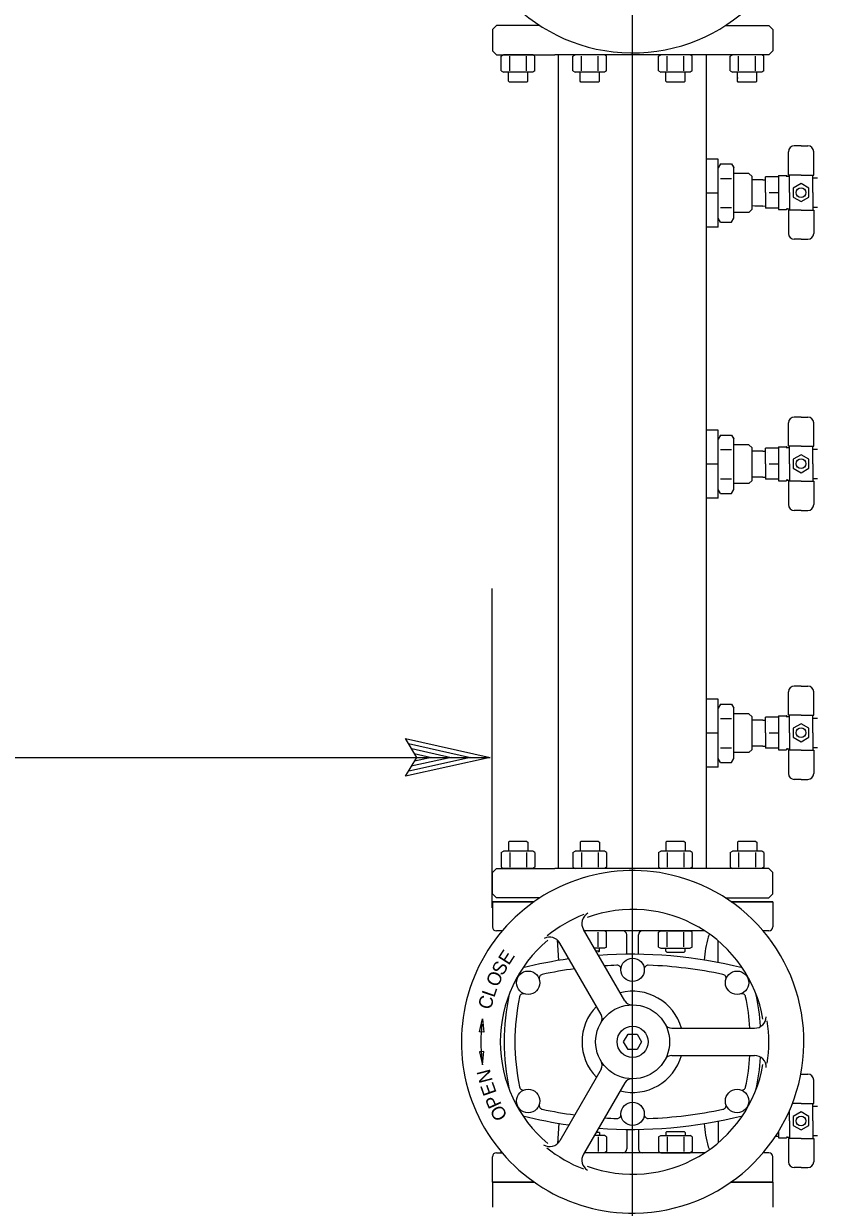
# Model space of a CAD drawing. Extents: x -1680 to 1155, y -802 to 799.
# Drawn here: x 260.1 to 316.4, y -477.7 to -393.8 of the extents above; entities that cross this region are included whole.
import ezdxf

# ---------------------------------------------------------------- set-up
doc = ezdxf.new("R2010")
doc.units = 0
doc.layers.add('Misc CnstDet(22)', color=7, linetype='Continuous')

msp = doc.modelspace()

# ---------------------------------------------------------------- linework, layer by layer
at = {"layer": 'Misc CnstDet(22)'}
for p, q in [((303.253, -548.827), (303.253, -300.878)), ((293.328, -394.194), (293.604, -393.918)), ((293.328, -394.194), (293.328, -395.711)), ((296.691, -393.918), (293.604, -393.918)), ((309.83, -393.918), (312.917, -393.918)), ((312.917, -393.918), (313.193, -394.194)), ((313.193, -394.194), (313.193, -395.711)), ((293.328, -395.711), (293.604, -395.987)), ((313.193, -395.711), (312.917, -395.987)), ((293.604, -395.987), (297.742, -395.987)), ((293.951, -396.08), (294.111, -395.987)), ((293.951, -397.131), (293.951, -396.08)), ((296.18, -395.987), (294.111, -395.987)), ((294.548, -397.128), (294.548, -396.082)), ((295.743, -397.128), (295.743, -396.082)), ((296.34, -396.08), (296.18, -395.987)), ((296.34, -397.131), (296.34, -396.08)), ((303.26, -395.987), (297.742, -395.987)), ((298.018, -397.253), (298.018, -395.987)), ((299.028, -396.08), (299.188, -395.987)), ((299.028, -397.131), (299.028, -396.08)), ((301.257, -395.987), (299.188, -395.987)), ((299.625, -397.128), (299.625, -396.082)), ((300.82, -397.128), (300.82, -396.082)), ((301.417, -396.08), (301.257, -395.987)), ((301.417, -397.131), (301.417, -396.08)), ((312.917, -395.987), (303.26, -395.987)), ((305.104, -396.08), (305.264, -395.987)), ((305.104, -397.131), (305.104, -396.08)), ((307.333, -395.987), (305.264, -395.987)), ((305.701, -397.128), (305.701, -396.082)), ((306.896, -397.128), (306.896, -396.082)), ((307.493, -396.08), (307.333, -395.987)), ((307.493, -397.131), (307.493, -396.08)), ((308.503, -397.253), (308.503, -395.987)), ((310.181, -396.08), (310.341, -395.987)), ((310.181, -397.131), (310.181, -396.08)), ((312.41, -395.987), (310.341, -395.987)), ((310.778, -397.128), (310.778, -396.082)), ((311.973, -397.128), (311.973, -396.082)), ((312.57, -396.08), (312.41, -395.987)), ((312.57, -397.131), (312.57, -396.08)), ((293.951, -397.131), (294.111, -397.223)), ((296.18, -397.223), (294.111, -397.223)), ((294.456, -397.852), (294.456, -397.223)), ((295.835, -397.852), (295.835, -397.223)), ((296.34, -397.131), (296.18, -397.223)), ((298.018, -453.652), (298.018, -397.253)), ((299.028, -397.131), (299.188, -397.223)), ((301.257, -397.223), (299.188, -397.223)), ((299.533, -397.852), (299.533, -397.223)), ((300.912, -397.852), (300.912, -397.223)), ((301.417, -397.131), (301.257, -397.223)), ((305.104, -397.131), (305.264, -397.223)), ((307.333, -397.223), (305.264, -397.223)), ((305.609, -397.852), (305.609, -397.223)), ((306.988, -397.852), (306.988, -397.223)), ((307.493, -397.131), (307.333, -397.223)), ((308.503, -453.652), (308.503, -397.253)), ((310.181, -397.131), (310.341, -397.223)), ((312.41, -397.223), (310.341, -397.223)), ((310.686, -397.852), (310.686, -397.223)), ((312.065, -397.852), (312.065, -397.223)), ((312.57, -397.131), (312.41, -397.223)), ((294.522, -397.918), (294.456, -397.852)), ((295.769, -397.918), (294.522, -397.918)), ((295.769, -397.918), (295.835, -397.852)), ((299.599, -397.918), (299.533, -397.852)), ((300.846, -397.918), (299.599, -397.918)), ((300.846, -397.918), (300.912, -397.852)), ((305.675, -397.918), (305.609, -397.852)), ((306.922, -397.918), (305.675, -397.918)), ((306.922, -397.918), (306.988, -397.852)), ((310.752, -397.664), (310.686, -397.597)), ((310.752, -397.918), (310.686, -397.852)), ((311.999, -397.918), (310.752, -397.918)), ((311.999, -397.918), (312.065, -397.852)), ((315.202, -402.437), (314.722, -402.437)), ((315.202, -402.437), (315.682, -402.437)), ((309.33, -403.37), (308.503, -403.37)), ((309.33, -408.198), (309.33, -403.37)), ((314.308, -404.506), (314.308, -402.851)), ((316.096, -404.506), (316.096, -402.851)), ((309.491, -403.722), (309.33, -404)), ((309.491, -403.722), (310.274, -403.722)), ((310.274, -403.722), (310.434, -404)), ((310.36, -403.853), (310.434, -403.982)), ((310.434, -407.568), (310.434, -403.982)), ((310.434, -407.568), (310.434, -403.982)), ((309.495, -404.74), (310.27, -404.74)), ((311.506, -404.396), (310.434, -404.397)), ((311.725, -404.616), (311.506, -404.396)), ((311.725, -406.934), (311.725, -404.616)), ((311.932, -404.848), (311.725, -404.854)), ((312.484, -404.848), (311.932, -404.848)), ((312.484, -404.848), (312.691, -404.854)), ((312.691, -405.748), (312.691, -404.644)), ((313.596, -404.644), (312.691, -404.644)), ((312.802, -404.954), (312.802, -404.954)), ((313.596, -404.644), (313.455, -404.644)), ((313.596, -404.544), (313.596, -406.952)), ((313.596, -404.544), (314.15, -404.544)), ((314.198, -404.544), (314.198, -404.544)), ((314.198, -404.644), (314.198, -404.578)), ((314.236, -404.596), (314.374, -404.596)), ((315.202, -404.506), (314.308, -404.506)), ((314.374, -405.748), (314.374, -404.506)), ((315.202, -404.506), (316.096, -404.506)), ((316.03, -405.748), (316.03, -404.506)), ((316.039, -404.713), (316.356, -404.713)), ((309.33, -405.784), (308.503, -405.784)), ((312.691, -405.748), (312.691, -406.852)), ((312.943, -405.748), (313.596, -405.748)), ((314.374, -405.748), (314.374, -406.99)), ((316.03, -405.748), (316.03, -406.99)), ((311.932, -406.702), (311.725, -406.696)), ((312.484, -406.702), (311.932, -406.702)), ((312.484, -406.702), (312.691, -406.696)), ((316.039, -406.783), (316.356, -406.783)), ((309.491, -407.846), (309.33, -407.568)), ((309.495, -406.81), (310.27, -406.81)), ((310.274, -407.846), (310.434, -407.568)), ((311.506, -407.153), (310.434, -407.153)), ((311.725, -406.934), (311.506, -407.153)), ((313.596, -406.852), (312.691, -406.852)), ((312.802, -406.808), (312.802, -406.808)), ((313.596, -406.952), (314.15, -406.952)), ((314.198, -406.852), (314.198, -406.918)), ((314.236, -406.9), (314.374, -406.9)), ((314.308, -406.99), (314.308, -408.645)), ((315.202, -406.99), (314.308, -406.99)), ((315.202, -406.99), (316.096, -406.99)), ((316.096, -406.99), (316.096, -408.645)), ((309.33, -408.198), (308.503, -408.198)), ((309.491, -407.846), (310.274, -407.846)), ((315.202, -409.059), (314.722, -409.059)), ((315.202, -409.059), (315.682, -409.059)), ((315.202, -421.653), (314.722, -421.653)), ((315.202, -421.653), (315.682, -421.653)), ((309.33, -422.586), (308.503, -422.586)), ((309.33, -427.414), (309.33, -422.586)), ((314.308, -423.722), (314.308, -422.067)), ((316.096, -423.722), (316.096, -422.067)), ((309.491, -422.938), (309.33, -423.216)), ((309.491, -422.938), (310.274, -422.938)), ((310.274, -422.938), (310.434, -423.216)), ((310.36, -423.069), (310.434, -423.198)), ((310.434, -426.784), (310.434, -423.198)), ((310.434, -426.784), (310.434, -423.198)), ((309.495, -423.956), (310.27, -423.956)), ((311.506, -423.613), (310.434, -423.613)), ((311.725, -423.832), (311.506, -423.613)), ((311.725, -426.15), (311.725, -423.832)), ((311.932, -424.064), (311.725, -424.07)), ((312.484, -424.064), (311.932, -424.064)), ((312.484, -424.064), (312.691, -424.07)), ((312.691, -424.964), (312.691, -423.86)), ((313.596, -423.86), (312.691, -423.86)), ((312.802, -424.17), (312.802, -424.17)), ((313.596, -423.86), (313.455, -423.86)), ((313.596, -423.76), (313.596, -426.168)), ((313.596, -423.76), (314.15, -423.76)), ((314.198, -423.76), (314.198, -423.76)), ((314.198, -423.86), (314.198, -423.794)), ((314.236, -423.812), (314.374, -423.812)), ((315.202, -423.722), (314.308, -423.722)), ((314.374, -424.964), (314.374, -423.722)), ((315.202, -423.722), (316.096, -423.722)), ((316.03, -424.964), (316.03, -423.722)), ((316.039, -423.929), (316.356, -423.929)), ((309.33, -425), (308.503, -425)), ((312.691, -424.964), (312.691, -426.068)), ((312.943, -424.964), (313.596, -424.964)), ((314.374, -424.964), (314.374, -426.206)), ((316.03, -424.964), (316.03, -426.206)), ((309.495, -426.026), (310.27, -426.026)), ((311.932, -425.918), (311.725, -425.912)), ((312.484, -425.918), (311.932, -425.918)), ((312.484, -425.918), (312.691, -425.912)), ((313.596, -426.068), (312.691, -426.068)), ((312.802, -426.024), (312.802, -426.024)), ((314.198, -426.068), (314.198, -426.134)), ((316.039, -425.999), (316.356, -425.999)), ((309.491, -427.062), (309.33, -426.784)), ((310.274, -427.062), (310.434, -426.784)), ((311.506, -426.37), (310.434, -426.369)), ((311.725, -426.15), (311.506, -426.37)), ((313.596, -426.168), (314.15, -426.168)), ((314.236, -426.116), (314.374, -426.116)), ((314.308, -426.206), (314.308, -427.861)), ((315.202, -426.206), (314.308, -426.206)), ((315.202, -426.206), (316.096, -426.206)), ((316.096, -426.206), (316.096, -427.861)), ((309.33, -427.414), (308.503, -427.414)), ((309.491, -427.062), (310.274, -427.062)), ((315.202, -428.275), (314.722, -428.275)), ((315.202, -428.275), (315.682, -428.275)), ((293.292, -433.812), (293.292, -456.425)), ((314.308, -442.784), (314.308, -441.128)), ((315.202, -440.714), (314.722, -440.714)), ((315.202, -440.714), (315.682, -440.714)), ((316.096, -442.784), (316.096, -441.128)), ((309.33, -441.647), (308.503, -441.647)), ((309.33, -446.475), (309.33, -441.647)), ((309.491, -442), (309.33, -442.277)), ((309.491, -442), (310.274, -442)), ((310.274, -442), (310.434, -442.277)), ((310.36, -442.13), (310.434, -442.259)), ((310.434, -445.845), (310.434, -442.259)), ((310.434, -445.845), (310.434, -442.259)), ((311.506, -442.674), (310.434, -442.674)), ((311.725, -442.893), (311.506, -442.674)), ((313.596, -442.821), (313.596, -445.229)), ((313.596, -442.821), (314.15, -442.821)), ((314.198, -442.821), (314.198, -442.821)), ((314.198, -442.921), (314.198, -442.855)), ((315.202, -442.784), (314.308, -442.784)), ((314.374, -444.025), (314.374, -442.784)), ((315.202, -442.784), (316.096, -442.784)), ((316.03, -444.025), (316.03, -442.784)), ((309.495, -443.017), (310.27, -443.017)), ((311.725, -445.211), (311.725, -442.893)), ((311.932, -443.125), (311.725, -443.131)), ((312.484, -443.125), (311.932, -443.125)), ((312.484, -443.125), (312.691, -443.131)), ((312.691, -444.025), (312.691, -442.921)), ((313.596, -442.921), (312.691, -442.921)), ((312.802, -443.231), (312.802, -443.231)), ((313.596, -442.921), (313.455, -442.921)), ((314.236, -442.873), (314.374, -442.873)), ((316.039, -442.99), (316.356, -442.99)), ((287.955, -445.777), (287.155, -444.437)), ((287.155, -444.437), (287.155, -444.437)), ((287.155, -444.437), (293.155, -445.777)), ((309.33, -444.061), (308.503, -444.061)), ((312.691, -444.025), (312.691, -445.129)), ((312.943, -444.025), (313.596, -444.025)), ((314.374, -444.025), (314.374, -445.267)), ((316.03, -444.025), (316.03, -445.267)), ((287.372, -444.793), (291.775, -445.776)), ((287.606, -445.152), (290.393, -445.775)), ((309.495, -445.088), (310.27, -445.088)), ((311.725, -445.211), (311.506, -445.431)), ((311.932, -444.979), (311.725, -444.973)), ((312.484, -444.979), (311.932, -444.979)), ((312.484, -444.979), (312.691, -444.973)), ((313.596, -445.129), (312.691, -445.129)), ((312.802, -445.085), (312.802, -445.085)), ((313.596, -445.229), (314.15, -445.229)), ((314.198, -445.129), (314.198, -445.195)), ((314.236, -445.177), (314.374, -445.177)), ((314.308, -445.267), (314.308, -446.922)), ((315.202, -445.267), (314.308, -445.267)), ((315.202, -445.267), (316.096, -445.267)), ((316.039, -445.06), (316.356, -445.06)), ((316.096, -445.267), (316.096, -446.922)), ((212.088, -445.777), (293.155, -445.777)), ((293.155, -445.777), (287.155, -447.107)), ((287.155, -447.107), (287.955, -445.777)), ((291.764, -445.78), (287.39, -446.748)), ((290.393, -445.775), (287.567, -446.401)), ((287.782, -445.499), (289.011, -445.774)), ((289.011, -445.774), (287.802, -446.041)), ((293.155, -445.777), (293.155, -445.777)), ((309.491, -446.123), (309.33, -445.845)), ((309.491, -446.123), (310.274, -446.123)), ((310.274, -446.123), (310.434, -445.845)), ((311.506, -445.431), (310.434, -445.43)), ((309.33, -446.475), (308.503, -446.475)), ((287.155, -447.107), (287.155, -447.107)), ((315.202, -447.336), (314.722, -447.336)), ((315.202, -447.336), (315.682, -447.336)), ((294.522, -451.721), (294.456, -451.787)), ((294.456, -451.787), (294.456, -452.416)), ((295.769, -451.721), (294.522, -451.721)), ((295.769, -451.721), (295.835, -451.787)), ((295.835, -451.787), (295.835, -452.416)), ((299.599, -451.721), (299.533, -451.787)), ((299.533, -451.787), (299.533, -452.416)), ((300.846, -451.721), (299.599, -451.721)), ((300.846, -451.721), (300.912, -451.787)), ((300.912, -451.787), (300.912, -452.416)), ((305.675, -451.721), (305.609, -451.787)), ((305.609, -451.787), (305.609, -452.416)), ((306.922, -451.721), (305.675, -451.721)), ((306.922, -451.721), (306.988, -451.787)), ((306.988, -451.787), (306.988, -452.416)), ((310.752, -451.721), (310.686, -451.787)), ((310.686, -451.787), (310.686, -452.416)), ((311.999, -451.721), (310.752, -451.721)), ((311.999, -451.721), (312.065, -451.787)), ((312.065, -451.787), (312.065, -452.416)), ((293.951, -452.508), (294.111, -452.416)), ((293.951, -452.508), (293.951, -453.559)), ((296.18, -452.416), (294.111, -452.416)), ((294.548, -452.51), (294.548, -453.557)), ((295.743, -452.51), (295.743, -453.557)), ((296.34, -452.508), (296.18, -452.416)), ((296.34, -452.508), (296.34, -453.559)), ((299.028, -452.508), (299.188, -452.416)), ((299.028, -452.508), (299.028, -453.559)), ((301.257, -452.416), (299.188, -452.416)), ((299.625, -452.51), (299.625, -453.557)), ((300.82, -452.51), (300.82, -453.557)), ((301.417, -452.508), (301.257, -452.416)), ((301.417, -452.508), (301.417, -453.559)), ((305.104, -452.508), (305.264, -452.416)), ((305.104, -452.508), (305.104, -453.559)), ((307.333, -452.416), (305.264, -452.416)), ((305.701, -452.51), (305.701, -453.557)), ((306.896, -452.51), (306.896, -453.557)), ((307.493, -452.508), (307.333, -452.416)), ((307.493, -452.508), (307.493, -453.559)), ((310.181, -452.508), (310.341, -452.416)), ((310.181, -452.508), (310.181, -453.559)), ((312.41, -452.416), (310.341, -452.416)), ((310.778, -452.51), (310.778, -453.557)), ((311.973, -452.51), (311.973, -453.557)), ((312.57, -452.508), (312.41, -452.416)), ((312.57, -452.508), (312.57, -453.559)), ((293.328, -453.927), (293.604, -453.652)), ((293.604, -453.652), (297.742, -453.652)), ((293.951, -453.559), (294.111, -453.652)), ((296.18, -453.652), (294.111, -453.652)), ((296.34, -453.559), (296.18, -453.652)), ((312.917, -453.652), (297.742, -453.652)), ((299.028, -453.559), (299.188, -453.652)), ((301.257, -453.652), (299.188, -453.652)), ((301.417, -453.559), (301.257, -453.652)), ((305.104, -453.559), (305.264, -453.652)), ((307.333, -453.652), (305.264, -453.652)), ((307.493, -453.559), (307.333, -453.652)), ((310.181, -453.559), (310.341, -453.652)), ((312.41, -453.652), (310.341, -453.652)), ((312.57, -453.559), (312.41, -453.652)), ((313.193, -453.927), (312.917, -453.652)), ((293.328, -455.445), (293.328, -453.927)), ((313.193, -455.445), (313.193, -453.927)), ((293.328, -455.445), (293.604, -455.721)), ((296.281, -455.997), (293.328, -455.997)), ((293.328, -455.997), (293.328, -457.79)), ((293.328, -455.997), (296.281, -455.997)), ((293.328, -455.997), (296.281, -455.997)), ((296.691, -455.721), (293.604, -455.721)), ((309.83, -455.721), (312.917, -455.721)), ((313.193, -455.997), (310.24, -455.997)), ((310.24, -455.997), (313.193, -455.997)), ((310.24, -455.997), (313.193, -455.997)), ((312.917, -455.721), (313.193, -455.445)), ((313.193, -455.997), (313.193, -457.79)), ((302.704, -463.033), (299.774, -457.96)), ((294.011, -458.066), (293.604, -458.066)), ((298.027, -460.158), (297.926, -458.712)), ((308.376, -458.066), (299.836, -458.066)), ((301.257, -458.066), (299.836, -458.066)), ((300.82, -459.207), (300.82, -458.161)), ((301.417, -458.159), (301.257, -458.066)), ((301.417, -459.21), (301.417, -458.159)), ((302.847, -459.724), (302.847, -458.342)), ((303.674, -459.724), (303.674, -458.342)), ((305.104, -458.159), (305.264, -458.066)), ((305.104, -459.21), (305.104, -458.159)), ((305.264, -458.066), (307.333, -458.066)), ((305.701, -459.207), (305.701, -458.161)), ((306.896, -459.207), (306.896, -458.161)), ((307.493, -458.159), (307.333, -458.066)), ((307.493, -459.21), (307.493, -458.159)), ((309.33, -460.31), (309.33, -458.777)), ((312.917, -458.066), (312.51, -458.066)), ((301.031, -463.999), (298.102, -458.925)), ((301.257, -459.302), (300.549, -459.302)), ((300.912, -459.512), (300.67, -459.512)), ((300.846, -459.578), (300.912, -459.512)), ((300.912, -459.512), (300.912, -459.302)), ((301.417, -459.21), (301.257, -459.302)), ((305.104, -459.21), (305.264, -459.302)), ((305.264, -459.302), (307.333, -459.302)), ((305.609, -459.512), (305.609, -459.302)), ((305.675, -459.578), (305.609, -459.512)), ((305.675, -459.578), (306.922, -459.578)), ((306.922, -459.578), (306.988, -459.512)), ((306.988, -459.512), (306.988, -459.302)), ((307.493, -459.21), (307.333, -459.302)), ((306.047, -464.964), (311.905, -464.964)), ((306.047, -466.895), (311.905, -466.895)), ((301.031, -467.86), (298.102, -472.933)), ((302.704, -468.825), (299.774, -473.899)), ((315.202, -468.221), (315.182, -468.221)), ((315.202, -468.221), (315.682, -468.221)), ((316.096, -470.29), (316.096, -468.635)), ((315.202, -470.29), (314.59, -470.29)), ((315.202, -470.29), (316.096, -470.29)), ((316.03, -471.532), (316.03, -470.29)), ((316.039, -470.497), (316.356, -470.497)), ((314.374, -471.532), (314.374, -470.814)), ((298.027, -471.701), (297.926, -473.147)), ((302.847, -472.135), (302.847, -473.517)), ((303.674, -472.135), (303.674, -473.517)), ((309.33, -471.549), (309.33, -473.082)), ((314.374, -471.532), (314.374, -472.774)), ((316.03, -471.532), (316.03, -472.774)), ((301.257, -472.557), (300.549, -472.557)), ((300.912, -472.347), (300.67, -472.347)), ((300.82, -472.652), (300.82, -473.698)), ((300.912, -472.347), (300.912, -472.557)), ((301.417, -472.649), (301.257, -472.557)), ((301.417, -472.649), (301.417, -473.7)), ((305.104, -472.649), (305.264, -472.557)), ((305.104, -472.649), (305.104, -473.7)), ((305.264, -472.557), (307.333, -472.557)), ((305.675, -472.281), (305.609, -472.347)), ((305.609, -472.347), (305.609, -472.557)), ((305.675, -472.281), (306.922, -472.281)), ((305.701, -472.652), (305.701, -473.698)), ((306.896, -472.652), (306.896, -473.698)), ((306.922, -472.281), (306.988, -472.347)), ((306.988, -472.347), (306.988, -472.557)), ((307.493, -472.649), (307.333, -472.557)), ((307.493, -472.649), (307.493, -473.7)), ((313.596, -472.636), (313.38, -472.636)), ((313.596, -472.297), (313.596, -472.736)), ((313.596, -472.736), (314.15, -472.736)), ((314.198, -472.636), (314.198, -472.702)), ((314.236, -472.684), (314.374, -472.684)), ((314.308, -472.774), (314.308, -474.429)), ((315.202, -472.774), (314.308, -472.774)), ((315.202, -472.774), (316.096, -472.774)), ((316.039, -472.567), (316.356, -472.567)), ((316.096, -472.774), (316.096, -474.429)), ((293.604, -473.793), (294.011, -473.793)), ((293.951, -473.793), (293.951, -473.721)), ((308.376, -473.793), (299.836, -473.793)), ((301.257, -473.793), (299.836, -473.793)), ((301.417, -473.7), (301.257, -473.793)), ((305.104, -473.7), (305.264, -473.793)), ((305.264, -473.793), (307.333, -473.793)), ((307.493, -473.7), (307.333, -473.793)), ((312.917, -473.793), (312.51, -473.793)), ((312.57, -473.793), (312.57, -473.721)), ((293.327, -475.345), (293.327, -474.069)), ((293.328, -475.862), (293.328, -474.069)), ((313.193, -475.862), (313.193, -474.069)), ((315.202, -474.843), (314.722, -474.843)), ((315.202, -474.843), (315.682, -474.843)), ((296.281, -475.862), (293.328, -475.862)), ((293.328, -475.862), (296.281, -475.862)), ((293.328, -475.862), (293.328, -477.655)), ((310.24, -475.862), (313.193, -475.862)), ((313.193, -475.862), (310.24, -475.862)), ((313.193, -475.862), (313.193, -477.655))]:
    msp.add_line(p, q, dxfattribs=at)
for points in [[(314.65, -406.067), (315.202, -406.385), (315.754, -406.067), (315.754, -405.429), (315.202, -405.111), (314.65, -405.429)], [(314.65, -425.283), (315.202, -425.601), (315.754, -425.283), (315.754, -424.645), (315.202, -424.327), (314.65, -424.645)], [(314.65, -444.344), (315.202, -444.662), (315.754, -444.344), (315.754, -443.706), (315.202, -443.388), (314.65, -443.706)], [(292.709, -465.239), (292.4, -465.216), (292.624, -464.299)], [(302.942, -466.481), (302.623, -465.929), (302.942, -465.378), (303.579, -465.378), (303.898, -465.929), (303.579, -466.481)], [(292.709, -466.619), (292.4, -466.643), (292.624, -467.56)], [(314.65, -471.851), (315.202, -472.169), (315.754, -471.851), (315.754, -471.213), (315.202, -470.895), (314.65, -471.213)]]:
    msp.add_lwpolyline(points, close=True, dxfattribs=at)
for centre, radius in [((315.202, -405.748), 0.345), ((315.202, -424.964), 0.345), ((315.202, -444.025), 0.345), ((303.26, -460.825), 0.828), ((295.855, -461.738), 0.828), ((310.666, -461.738), 0.828), ((303.26, -465.929), 2.621), ((303.26, -465.929), 1.104), ((295.855, -470.12), 0.828), ((310.666, -470.12), 0.828), ((303.26, -471.034), 0.828), ((315.202, -471.532), 0.345)]:
    msp.add_circle(centre, radius, dxfattribs=at)
for centre, radius, start, end in [((303.26, -383.709), 12.14, 89.41089, 89.36318), ((314.722, -402.851), 0.414, 90, 180), ((315.682, -402.851), 0.414, 0, 90), ((314.15, -404.592), 0.0482, 27.27961, 90), ((314.236, -404.548), 0.0482, 207.27961, 270), ((316.039, -404.679), 0.0345, 254.17334, 270), ((314.15, -406.904), 0.0482, 270, 332.72039), ((314.236, -406.948), 0.0482, 90, 152.72039), ((314.722, -408.645), 0.414, 180, 270), ((315.682, -408.645), 0.414, 270, 0), ((314.722, -422.067), 0.414, 90, 180), ((315.682, -422.067), 0.414, 0, 90), ((314.15, -423.808), 0.0482, 27.27961, 90), ((314.236, -423.764), 0.0482, 207.27961, 270), ((316.039, -423.895), 0.0345, 254.17334, 270), ((314.15, -426.12), 0.0482, 270, 332.72039), ((314.236, -426.164), 0.0482, 90, 152.72039), ((314.722, -427.861), 0.414, 180, 270), ((315.682, -427.861), 0.414, 270, 0), ((314.722, -441.128), 0.414, 90, 180), ((315.682, -441.128), 0.414, 0, 90), ((314.15, -442.869), 0.0482, 27.27961, 90), ((314.236, -442.825), 0.0482, 207.27961, 270), ((316.039, -442.956), 0.0345, 254.17334, 270), ((314.15, -445.181), 0.0482, 270, 332.72039), ((314.236, -445.225), 0.0482, 90, 152.72039), ((314.722, -446.922), 0.414, 180, 270), ((315.682, -446.922), 0.414, 270, 0), ((303.26, -465.929), 12.14, 76.86344, 270.73474), ((303.26, -465.929), 12.14, 270.91058, 76.86344), ((303.26, -465.929), 9.657, 110.95405, 128.82668), ((300.491, -457.546), 0.828, 118.68649, 210), ((303.26, -465.929), 9.381, 9.89685, 110.10315), ((293.604, -457.79), 0.276, 180, 270), ((312.917, -457.79), 0.276, 270, 0), ((303.26, -465.929), 9.381, 129.89685, 230.10315), ((297.385, -459.339), 0.828, 30, 118.20849), ((302.571, -458.342), 0.276, 0, 90), ((303.95, -458.342), 0.276, 90, 180), ((319.04, -461.211), 10.771, 165.42389, 174.23965), ((309.523, -458.783), 0.95, 148.95843, 162.68618), ((303.26, -491.313), 31.591, 98.21165, 104.26664), ((303.26, -491.313), 31.591, 75.73336, 94.38547), ((296.912, -461.423), 0.276, 101.99082, 196.60744), ((303.26, -491.313), 30.833, 97.64692, 101.99082), ((303.26, -491.313), 30.833, 92.06777, 93.70755), ((302.158, -460.776), 0.276, 357.45115, 92.06778), ((304.363, -460.776), 0.276, 87.93223, 182.54885), ((303.26, -491.313), 30.833, 78.00918, 87.93223), ((309.609, -461.423), 0.276, 343.39256, 78.00918), ((310.308, -465.929), 16.152, 167.84886, 192.15114), ((310.308, -465.929), 15.393, 168.01395, 180), ((295.52, -462.79), 0.276, 72.34046, 168.01395), ((303.26, -465.929), 3.587, 15.6185, 104.3815), ((311.001, -462.79), 0.276, 11.98605, 107.65954), ((296.213, -465.929), 15.393, 3.59672, 11.98605), ((296.213, -465.929), 16.152, 3.93153, 12.15114), ((303.26, -465.929), 3.587, 135.6185, 224.3815), ((303.181, -462.757), 0.552, 210, 271.42812), ((300.553, -464.275), 0.552, 328.57188, 30), ((311.905, -464.136), 0.828, 270, 358.20849), ((303.26, -465.929), 9.657, 350.95405, 8.82668), ((303.26, -465.929), 10.76, 173.28613, 186.71387), ((306.047, -464.412), 0.552, 208.57188, 270), ((310.308, -465.929), 15.393, 180, 191.98605), ((303.26, -465.929), 3.587, 255.6185, 344.3815), ((306.047, -467.447), 0.552, 90, 151.42812), ((296.213, -465.929), 15.393, 348.01395, 356.40328), ((311.905, -467.723), 0.828, 358.68649, 90), ((296.213, -465.929), 16.152, 347.84886, 356.06847), ((303.26, -465.929), 9.381, 249.89685, 350.10315), ((300.553, -467.584), 0.552, 330, 31.42812), ((303.181, -469.101), 0.552, 88.57188, 150), ((315.682, -468.635), 0.414, 0, 90), ((295.52, -469.069), 0.276, 191.98605, 287.65954), ((311.001, -469.069), 0.276, 252.34046, 348.01395), ((296.912, -470.436), 0.276, 163.39256, 258.00918), ((309.609, -470.436), 0.276, 281.99082, 16.60744), ((316.039, -470.463), 0.0345, 254.17334, 270), ((303.26, -440.546), 31.591, 255.73336, 261.78835), ((303.26, -440.546), 30.833, 258.00918, 262.35308), ((303.26, -440.546), 31.591, 265.61453, 284.26664), ((303.26, -440.546), 30.833, 266.29245, 267.93223), ((302.158, -471.083), 0.276, 267.93223, 2.54885), ((304.363, -471.083), 0.276, 177.45115, 272.06777), ((303.26, -440.546), 30.833, 272.06777, 281.99082), ((319.04, -470.648), 10.771, 185.76035, 194.57611), ((297.385, -472.519), 0.828, 238.68649, 330), ((314.15, -472.688), 0.0482, 270, 332.72039), ((314.236, -472.732), 0.0482, 90, 152.72039), ((293.604, -474.069), 0.276, 90, 180), ((303.26, -465.929), 9.657, 230.95405, 248.82668), ((302.571, -473.517), 0.276, 270, 0), ((303.95, -473.517), 0.276, 180, 270), ((309.523, -473.076), 0.95, 197.31382, 211.04157), ((312.917, -474.069), 0.276, 0, 90), ((300.491, -474.313), 0.828, 150, 238.20849), ((314.722, -474.429), 0.414, 180, 270), ((315.682, -474.429), 0.414, 270, 0), ((293.051, -475.345), 0.276, 348.23171, 0)]:
    msp.add_arc(centre, radius, start, end, dxfattribs=at)

# ---------------------------------------------------------------- texts
for s, rotation, p in [('E', 57.32318, (294.482, -460.551)), ('S', 62.01068, (294.069, -461.301)), ('O', 66.69818, (293.711, -462.105)), ('C', 76.07318, (293.222, -463.691)), ('L', 71.38568, (293.45, -462.832)), ('N', 104.33908, (293.352, -468.698)), ('E', 109.33908, (293.635, -469.535)), ('P', 114.33908, (293.993, -470.371)), ('O', 119.33908, (294.428, -471.186))]:
    msp.add_text(s, height=0.966, rotation=rotation, dxfattribs=at).set_placement(p)

doc.saveas('drawing.dxf')
